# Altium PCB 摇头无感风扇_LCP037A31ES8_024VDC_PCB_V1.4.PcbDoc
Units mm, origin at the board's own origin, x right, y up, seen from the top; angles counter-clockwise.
Board outline 42.25 x 44.25 mm, 2 copper layers (Top Layer, Bottom Layer); 69 components, 48 nets, 179 pads, 190 vias.
Unrouted connection lines stored in the file: 31.
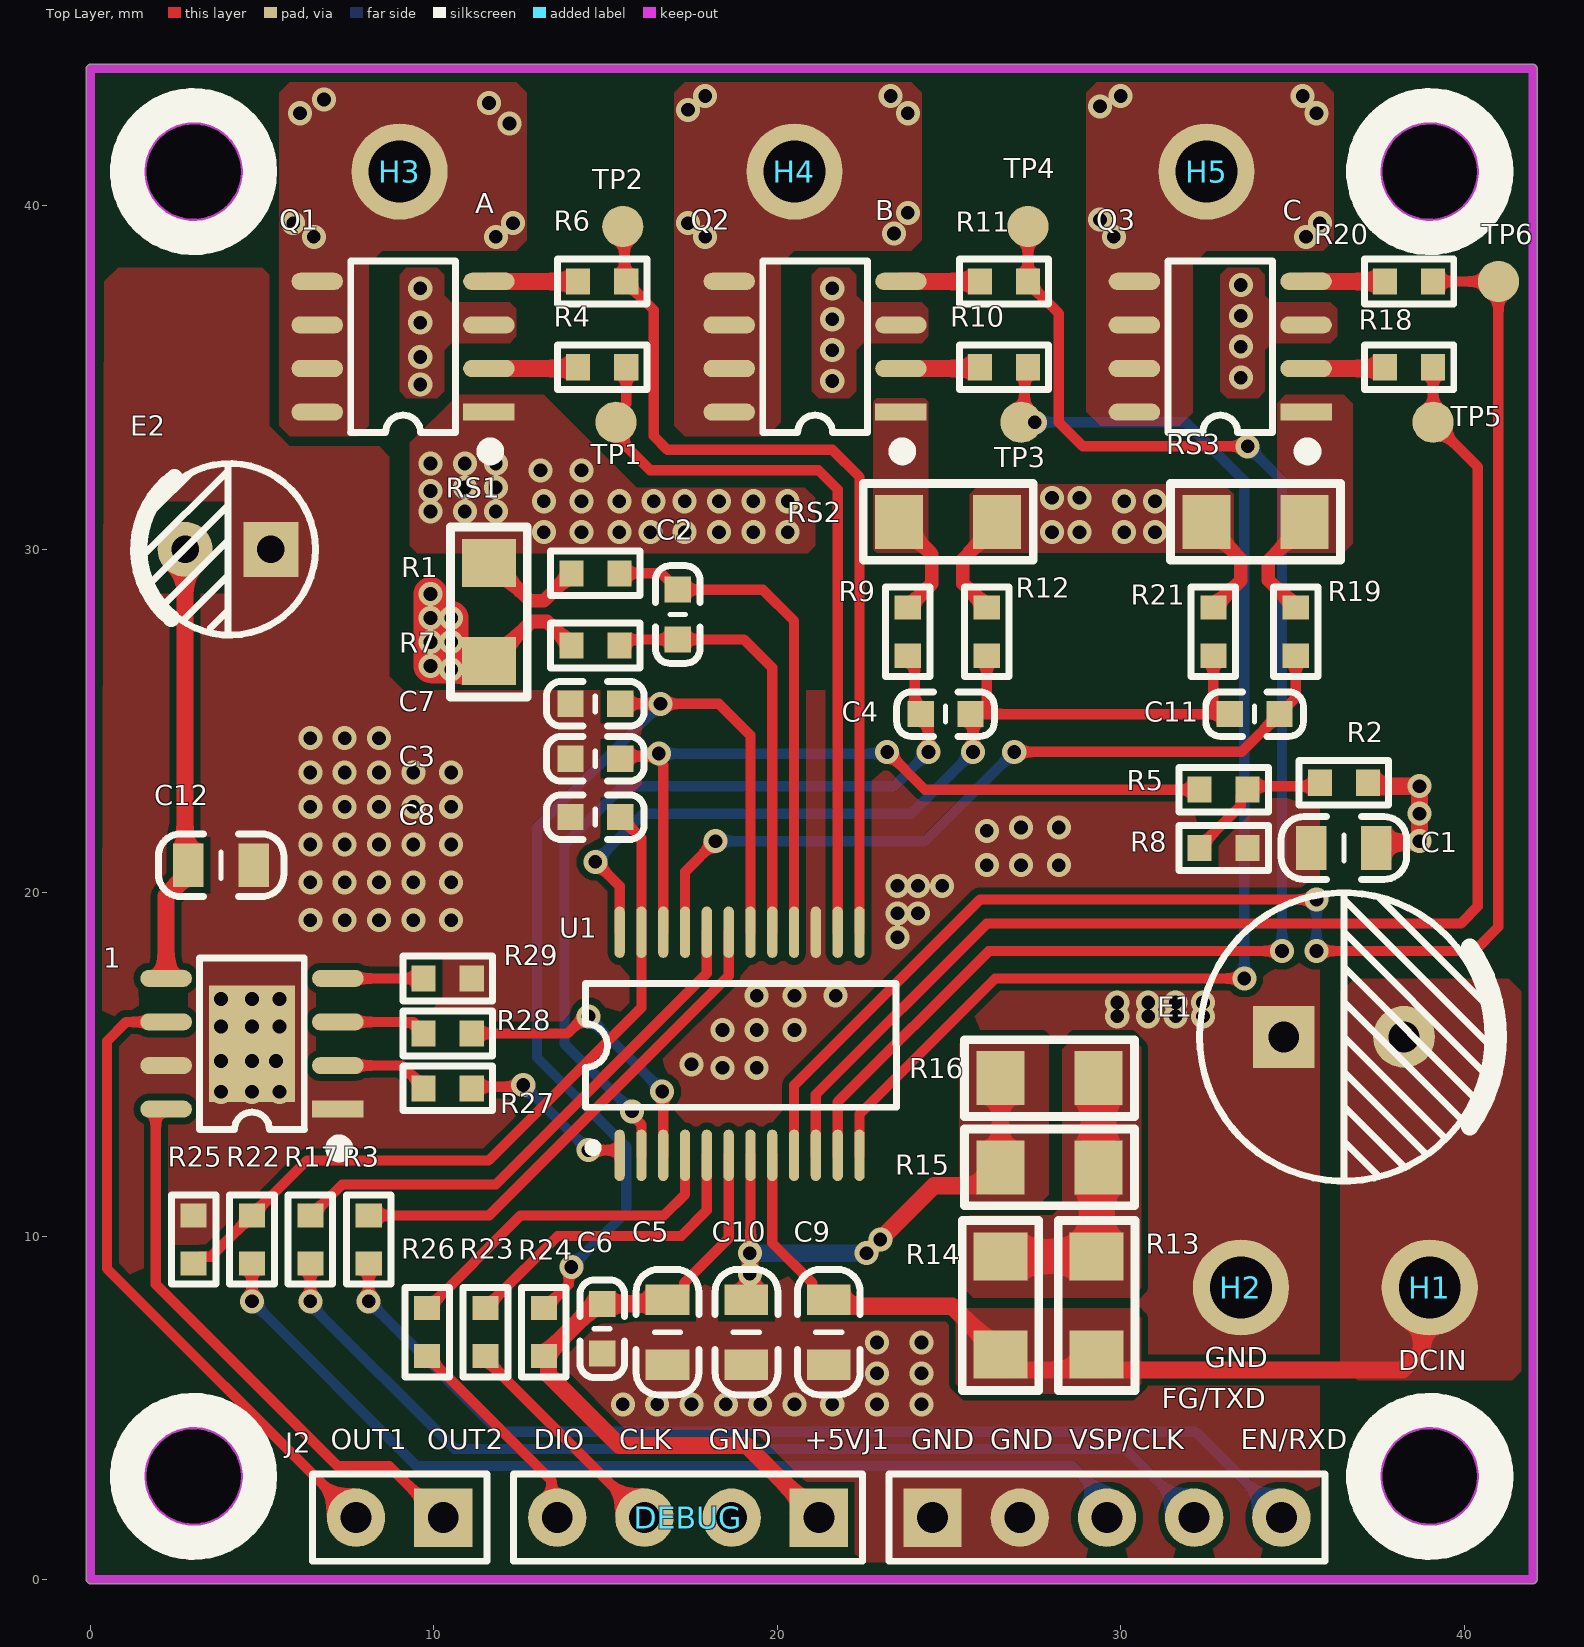
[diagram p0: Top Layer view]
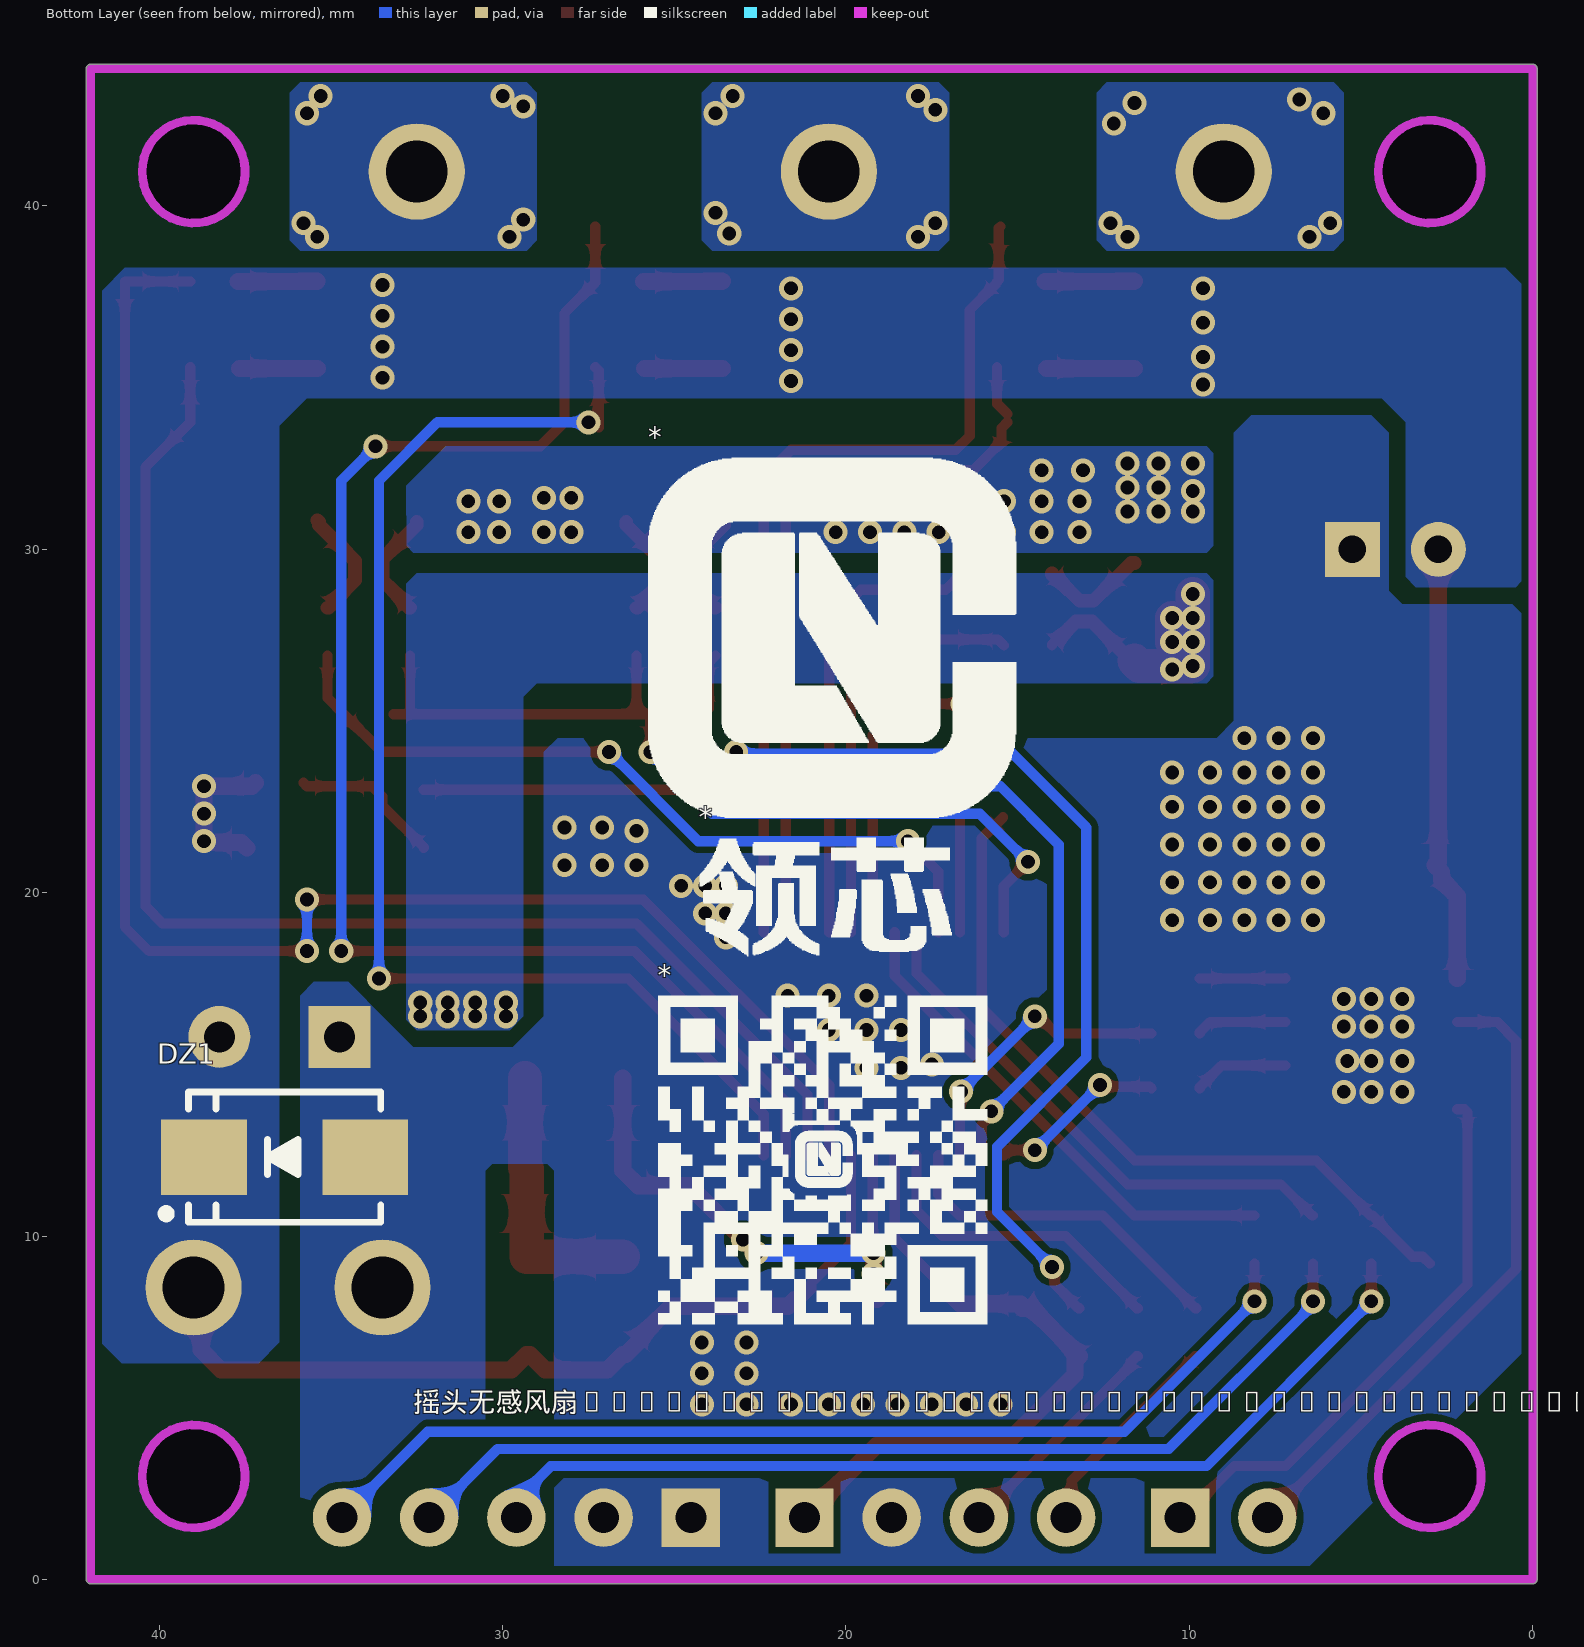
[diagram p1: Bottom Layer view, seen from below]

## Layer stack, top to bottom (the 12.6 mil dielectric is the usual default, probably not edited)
Top Solder: solder mask 0.0102, Solder Resist, Dk 3.5
Top Layer: signal copper 0.0356
Dielectric 1: dielectric 0.32, FR-4, Dk 4.8
Bottom Layer: signal copper 0.0356
Bottom Solder: solder mask 0.0102, Solder Resist, Dk 3.5

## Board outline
0,-0.127 cw(c0,0) -0.127,0 -0.127,44 cw(c0,44) 0,44.127 42,44.127 cw(c42,44) 42.127,44 42.127,0 cw(c42,0) 42,-0.127
cut-out: 37.5,3 ccw(c39,3) 39,1.5 ccw(c39,3) 40.5,3 ccw(c39,3) 39,4.5 ccw(c39,3)
cut-out: 3,1.5 cw(c3,3) 1.5,3 cw(c3,3) 3,4.5 cw(c3,3) 4.5,3 cw(c3,3)
cut-out: 39,39.5 cw(c39,41) 37.5,41 cw(c39,41) 39,42.5 cw(c39,41) 40.5,41 cw(c39,41)
cut-out: 3,39.5 cw(c3,41) 1.5,41 cw(c3,41) 3,42.5 cw(c3,41) 4.5,41 cw(c3,41)
cut-out: 1.5,3 ccw(c3,3) 3,1.5 ccw(c3,3) 4.5,3 ccw(c3,3) 3,4.5 ccw(c3,3)
cut-out: 37.5,41 ccw(c39,41) 39,39.5 ccw(c39,41) 40.5,41 ccw(c39,41) 39,42.5 ccw(c39,41)
cut-out: 1.5,41 ccw(c3,41) 3,39.5 ccw(c3,41) 4.5,41 ccw(c3,41) 3,42.5 ccw(c3,41)

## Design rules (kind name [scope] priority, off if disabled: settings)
Clearance [All] p1: gap=0.2 ignorepadtopadclearanceinfootprint=TRUE
ComponentClearance [All] p1: gap=0.15 collisioncheckmode=3 verticalgap=0.254 showdistances=FALSE
Height [All] p1: minheight=0 maxheight=200 prefheight=12.7
MinimumSolderMaskSliver [All] p1: minsoldermaskwidth=0.12
PlaneConnect [All] p1: planeconnectstyle=Direct reliefexpansion=0.508 reliefentries=4 reliefconductorwidth=0.254 reliefairgap=0.254
PolygonConnect [All] p1: connectstyle=Direct reliefconductorwidth=0.254 reliefentries=4 polygonreliefangle="90 Angle" airgapwidth=0.254
RoutingVias [All] p1: holewidth=0.4 width=0.7 viastyle="Through Hole" minholewidth=0.305 minwidth=0.508 maxholewidth=0.711 maxwidth=1.27
SilkToSilkClearance [All] p1: silktosilkclearance=0.1
SilkToSolderMaskClearance [IsPad] p1: minsilkscreentomaskgap=0.05 clearancetoexposedcopper=TRUE
SolderMaskExpansion [IsVia] p1: expansion=0.102 istentingtop=TRUE useseparateexpansions=TRUE expansionbottom=0.102 istentingbottom=TRUE
Width [All] p1: maxlimit=1.27 minlimit=0.2 preferedwidth=0.3
24 further rules are at their usual default settings.

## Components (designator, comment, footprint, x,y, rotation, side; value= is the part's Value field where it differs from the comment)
1 "KP8110X" SOP-8_150_50-1 4.7,15.6 r180 top
* "LOGO-TU" LOGO-TU 20.4,26.5 r180 bottom
* "LOGO-ZI" LOGO-ZI 20.6,20.1 r180 bottom
* "LOGO-MA" LOGO-MA 20.6,12.2 r180 bottom
C1 "104/50V" C0805 36.5,21.3 r0 top
C2 "101/50V" C0603 17.1,28.1 r90 top
C3 "103/50V" C0603 14.7,23.9 r0 top
C4 "101/50V" C0603 24.9,25.2 r180 top
C5 "106/50V" C0805 16.8,7.2 r90 top
C6 "104/50V" C0603 14.9,7.3 r90 top
C7 "104/50V" C0603 14.7,25.5 r0 top
C8 "101/50V" C0603 14.7,22.2 r0 top
C9 "104/50V" C0805 21.5,7.2 r90 top
C10 "105/50V" C0805 19.1,7.2 r90 top
C11 "101/50V" C0603 33.9,25.2 r0 top
C12 "104/50V" C0805 3.8,20.8 r0 top
DEBUG "CON4-a" PZ2.54-D-4P 17.4,1.8 r180 top
DZ1 "28V" SMB 36.35,12.3 r0 bottom
E1 "220uF/35V" CE-3.5-8 36.5,15.8 r0 top
E2 "100uF/35V" CE-2.5-5 4,30 r180 top
H1 "DCIN" HOLD-16AWG 39,8.5 r0 top
H2 "GND" HOLD-16AWG 33.5,8.5 r0 top
H3 "A" HOLD-16AWG 9,41 r0 top
H4 "B" HOLD-16AWG 20.5,41 r0 top
H5 "C" HOLD-16AWG 32.5,41 r0 top
J1 "CON5" PZ2.54-D-5P 29.6,1.8 r0 top
J2 "CON2" PZ2.54-D-2P 9,1.8 r180 top
Q1 "4606" SOP-8_150_50 9.1,35.9 r180 top
Q2 "4606" SOP-8_150_50 21.1,35.9 r180 top
Q3 "4606" SOP-8_150_50 32.9,35.9 r180 top
R1 "68R" R0603 14.7,29.3 r0 top
R2 "100K" R0603 36.5,23.2 r0 top
R3 "1K" R0603 8.1,9.9 r90 top
R4 "51R" R0603 14.9,35.3 r180 top
R5 "1K" R0603 33,23 r180 top
R6 "51R" R0603 14.9,37.8 r180 top
R7 "68R" R0603 14.7,27.2 r0 top
R8 "10K" R0603 33,21.3 r180 top
R9 "68R" R0603 23.8,27.6 r270 top
R10 "51R" R0603 26.6,35.3 r180 top
R11 "51R" R0603 26.6,37.8 r180 top
R12 "68R" R0603 26.1,27.6 r270 top
R13 "1K/1206" R1206 29.3,8 r270 top
R14 "1K/1206" R1206 26.5,8 r270 top
R15 "680R/1206" R1206 27.9,12 r0 top
R16 "680R/1206" R1206 27.9,14.6 r0 top
R17 "10K" R0603 6.4,9.9 r90 top
R18 "51R" R0603 38.4,35.3 r180 top
R19 "68R" R0603 35.1,27.6 r270 top
R20 "51R" R0603 38.4,37.8 r180 top
R21 "68R" R0603 32.7,27.6 r270 top
R22 "1K" R0603 4.7,9.9 r90 top
R23 "100R" R0603 11.5,7.2 r90 top
R24 "10K" R0603 13.2,7.2 r270 top
R25 "10K" R0603 3,9.9 r270 top
R26 "100R" R0603 9.8,7.2 r90 top
R27 "1K" R0603 10.4,14.3 r180 top
R28 "1K" R0603 10.4,15.9 r180 top
R29 "1K" R0603 10.4,17.5 r180 top
RS1 "0.05R/1206" R1206 11.6,28.15 r90 top
RS2 "0.05R/1206" R1206 25,30.8 r180 top
RS3 "0.05R/1206" R1206 33.9,30.8 r0 top
TP1 "TEST" "TP 1.2" 15.3,33.7 r90 top
TP2 "TEST" "TP 1.2" 15.5,39.4 r90 top
TP3 "TEST" "TP 1.2" 27.1,33.7 r90 top
TP4 "TEST" "TP 1.2" 27.3,39.4 r90 top
TP5 "TEST" "TP 1.2" 39.1,33.7 r90 top
TP6 "TEST" "TP 1.2" 41,37.8 r90 top
U1 "LCP037A31ES8" LNCP-SSOP24-0.635 18.9,15.6 r90 top locked

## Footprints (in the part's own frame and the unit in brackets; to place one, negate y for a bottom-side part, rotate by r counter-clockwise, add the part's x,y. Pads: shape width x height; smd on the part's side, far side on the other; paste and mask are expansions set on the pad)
C0603 [mil] "0.5/2.1"
  rect 30x30 smd: 1(-28.54,0) 2(28.54,0)
  silkscreen extent -56,-26 56,26, body extent -31,-16 32,16, height 33
C0805 [mil] "贴片MLCC电容"
  rect 35x50 smd: 1(-37.4,0) 2(37.4,0)
  silkscreen extent -72,-36 72,36, body extent -39,-24 39,24, height 22
CE-2.5-5 [mm] "直插电解电容-脚距2.5mm直径5mm高度11mm"
  rect 1.6x1.6 hole 0.8: 1(-1.25,0)
  round 1.6 hole 0.8: 2(1.25,0)
  silkscreen extent -2.55,-2.5 2.6,2.5, body extent -2.5,-2.5 2.51,2.5, height 11.14
CE-3.5-8 [mm] "脚距3.5mm直径8mm高度11.5mm"
  rect 1.8x1.8 hole 0.9: 1(-1.75,0)
  round 1.8 hole 0.9: 2(1.75,0)
  silkscreen extent -4.2,-4.2 4.5,4.2, body extent -4,-4 4.01,4, height 11.64
HOLD-16AWG [mm] "1.8mm"
  round 2.8 hole 1.8: 1(0,0)
LNCP-SSOP24-0.635 [mm] "电机专用MCU-LCP037AH31E(X)S8/LCP018AH31E(X)S8"
  oval 1.5x0.3 smd: 1(-3.25,3.492) 2(-3.25,2.857) 3(-3.25,2.222) 4(-3.25,1.587) 5(-3.25,0.952) 6(-3.25,0.317) 7(-3.25,-0.318) 8(-3.25,-0.953) 9(-3.25,-1.588) 10(-3.25,-2.223) 11(-3.25,-2.858) 12(-3.25,-3.492) 13(3.25,-3.492) 14(3.25,-2.857) 15(3.25,-2.222) 16(3.25,-1.587) 17(3.25,-0.952) 18(3.25,-0.317) 19(3.25,0.318) 20(3.25,0.953) 21(3.25,1.588) 22(3.25,2.223) 23(3.25,2.858) 24(3.25,3.492)
  silkscreen extent -3.15,-4.57 1.75,4.48
LOGO-MA [mm]
  silkscreen extent -4.87,-4.77 4.71,4.78
LOGO-TU [mm]
  silkscreen extent -5.36,-4.32 5.36,6.15
LOGO-ZI [mm]
  silkscreen extent -3.67,-1.95 3.67,1.48
PZ2.54-D-2P [mm]
  rect 1.7x1.7 hole 0.9: 1(-1.27,0)
  round 1.7 hole 0.9: 2(1.27,0)
  silkscreen extent -2.54,-1.27 2.54,1.27, body extent -2.54,-1.27 2.54,1.27, height 2.54
PZ2.54-D-4P [mm]
  rect 1.7x1.7 hole 0.9: 1(-3.81,0)
  round 1.7 hole 0.9: 2(-1.27,0) 3(1.27,0) 4(3.81,0)
  silkscreen extent -5.08,-1.27 5.08,1.27, body extent -5.08,-1.27 5.08,1.27, height 2.54
PZ2.54-D-5P [mm]
  rect 1.7x1.7 hole 0.9: 1(-5.08,0)
  round 1.7 hole 0.9: 2(-2.54,0) 3(0,0) 4(2.54,0) 5(5.08,0)
  silkscreen extent -6.35,-1.27 6.35,1.27, body extent -6.35,-1.27 6.35,1.27, height 2.54
R0603 [mm] "0.5/2.1"
  rect 0.7x0.762 smd: 1(-0.7,0) 2(0.7,0)
  silkscreen extent -1.3,-0.65 1.3,0.65, body extent -0.8,-0.4 0.8,0.4, height 0.4
R1206 [mil] "1/4W贴片电阻"
  rect 55x62 smd: 1(-55.12,0) 2(57.09,0)
  silkscreen extent -96,-44 98,44, body extent -63,-31 63,32, height 22
SMB [mm] "4.7*3.9*2.2mm"
  rect 2.5x2.2 smd: 1(-2.35,0) 2(2.35,0)
  silkscreen extent -2.8,-1.9 3.58,1.9, body extent -2.65,-1.8 2.65,1.8, height 2.35
SOP-8_150_50 [mm] "无焊盘"
  rect 1.5x0.5 smd: 1(-2.5,1.905)
  oval 1.5x0.5 smd: 2(-2.5,0.635) 3(-2.5,-0.635) 4(-2.5,-1.905) 5(2.5,-1.905) 6(2.5,-0.635) 7(2.5,0.635) 8(2.5,1.905)
  silkscreen extent -2.69,-2.5 1.52,3.2, body extent -3,-2.5 3,2.5
SOP-8_150_50-1 [mm] "5*6*1.8mm（长宽高）"
  rect 1.5x0.5 smd: 1(-2.5,1.905)
  oval 1.5x0.5 smd: 2(-2.5,0.635) 3(-2.5,-0.635) 4(-2.5,-1.905) 5(2.5,-1.905) 6(2.5,-0.635) 7(2.5,0.635) 8(2.5,1.905)
  rect 2.5x3.4 smd paste-2: 9(0,0)
  rect 0.9x0.7 on Top Paste: 10(-0.625,1.1) 10(-0.625,0) 10(-0.625,-1.1) 11(0.65,1.1) 11(0.65,0) 11(0.65,-1.1)
  silkscreen extent -2.69,-2.5 1.52,3.2, body extent -3,-2.5 3,2.5
"TP 1.2" [mm] "测试点1.2mm"
  round 1.2 smd paste-1.2: 1(0,0)

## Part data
C1 C5 C9 C10 C12: library part CAP_8, "0805"
C2 C3 C4 C6 C7 C8 C11: library part CAP_4/6, "0402/0603"
DEBUG: "烧录口"
DZ1: library part DIO_ZENER, "稳压管"
E1 E2: library part CAP_CE, "直插电解电容"
H1 H2 H3 H4 H5: library part HOLD
J1 J2: "排针排母"
Q1 Q2 Q3: library part TRA_MOS_8D, "8脚合封组合"
R1 R2 R3 R4 R5 R6 R7 R8 R9 R10 R11 R12 R17 R18 R19 R20 R21 R22 R23 R24 R25 R26 R27 R28 R29: library part RES_4/6, "0402/0603"
R13 R14 R15 R16 RS1 RS2 RS3: library part RES_12/18, "1206/1802"
TP1 TP2 TP3 TP4 TP5 TP6: library part TEST1, "测试点"
U1: library part MCU_电机专用-5, "LCP037A"

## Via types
v1: diameter 0.7, hole 0.4, Top Layer to Bottom Layer, tented both sides, 190 vias

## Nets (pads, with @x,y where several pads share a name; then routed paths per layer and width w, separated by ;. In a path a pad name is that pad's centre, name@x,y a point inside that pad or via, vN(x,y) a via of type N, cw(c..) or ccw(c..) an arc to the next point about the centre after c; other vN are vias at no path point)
+5V: C5.2 C6.2 DEBUG.1 R24.2 U1.6 | length 19.5
  Top Layer w0.3: C5.2@16.869,8.219 17.059,8.219 17.285,8.444 17.285,8.635 18.583,9.932 U1.6
  Top Layer w0.5: C6.2@14.9,7.925 14.869,7.894 14.594,7.894 13.331,6.631 13.331,6.6 R24.2@13.231,6.5 ; C6.2 16.675,8.025 C5.2@16.869,8.219 ; DEBUG.1 19.11,3.9 15.4,3.9 13.331,5.969 13.331,6.4 R24.2@13.231,6.5 ; R24.2@13.231,6.5 R24.2 R24.2@13.231,6.5
+24V: 1.5 C1.2 C9.2 C12.1 DZ1.2 E1.2 E2.2 H1.1 Q1.3 Q2.3 Q3.3 R2.2 R13.2 R14.2 U1.8 | length 42.9
  Top Layer w0.3: U1.8 19.853,9.798 21.015,8.635 21.015,8.444 21.31,8.15 C9.2
  Top Layer w0.5: 1.5 2.2,19.9 2.655,20.355 2.655,20.605 C12.1 2.75,20.9 E2.2 ; C9.2 21.695,7.955 25.095,7.955 25.963,7.087 25.963,6.999 R14.2@26.411,6.55 ; R14.2 26.949,6.101 27.329,6.101 27.33,6.1 28.761,6.1 29.211,6.55 R13.2 29.749,6.101 30.129,6.101 30.13,6.1 38.2,6.1 38.78,6.68 38.78,8.28 H1.1 ; R2.2 37.3,23.1 v1(38.7,23.1) v1(38.7,22.3) v1(38.7,21.5) 38.662,21.462 37.612,21.462 C1.2
  other v1: 9.6,34.8 21.6,34.9 33.5,35 9.6,35.6 21.6,35.8 33.5,35.9 9.6,36.6 21.6,36.7 33.5,36.8 9.6,37.6 21.6,37.6 33.5,37.7
AH: R20.1 TP6.1 U1.9 | length 47.3
  Top Layer w0.3: U1.9 20.488,14.387 25.9,19.8 v1(35.7,19.8) ; v1(35.7,18.3) 40.3,18.3 41,19 TP6.1 R20.1
  Bottom Layer w0.3: v1(35.7,18.3) v1(35.7,19.8)
AL: R18.1 TP5.1 U1.10 | length 39.6
  Top Layer w0.3: U1.10 21.123,14.122 26.1,19.1 39.9,19.1 40.4,19.6 40.4,32.4 TP5.1 R18.1
BH: R11.1 TP4.1 U1.11 | length 43.3
  Top Layer w0.3: U1.11 21.758,13.905 26.153,18.3 v1(34.7,18.3) ; TP4.1 R11.1 27.3,37.769 28.2,36.869 28.2,33.7 28.9,33 v1(33.7,33)
  Bottom Layer w0.3: v1(33.7,33) 34.7,32 v1(34.7,18.3)
BL: R10.1 TP3.1 U1.12 | length 37.5
  Top Layer w0.3: U1.12 22.393,13.55 26.342,17.5 v1(33.6,17.5) ; R10.1 27.2,35.2 27.2,33.55 27.35,33.7 v1(27.5,33.7)
  Bottom Layer w0.3: v1(27.5,33.7) 31.9,33.7 33.6,32 v1(33.6,17.5)
CH: R6.1 TP2.1 U1.13 | length 26.2
  Top Layer w0.3: TP2.1 15.55,39.35 15.55,37.85 R6.1 15.6,37.769 16.4,36.969 16.4,33.3 16.8,32.9 21.6,32.9 22.393,32.107 U1.13
CL: R4.1 TP1.1 U1.14 | length 21.9
  Top Layer w0.3: TP1.1 15.472,33.528 15.472,33.128 16.3,32.3 21.2,32.3 21.758,31.743 U1.14 ; TP1.1@15.3,33.944 15.6,34.244 R4.1
EN/RXD: R3.2 U1.19 | length 14.6
  Top Layer w0.3: R3.2 11.607,10.6 18.583,17.575 U1.19
FG/TXD: R17.2 U1.20 | length 15.7
  Top Layer w0.3: R17.2 6.431,10.6 7.331,11.5 11.8,11.5 17.948,17.648 U1.20
GND: 1.1 1.7 1.9 C1.1 C3.1 C5.1 C6.1 C7.1 C8.1 C9.1 C10.1 C12.2 DEBUG.2 DZ1.1 E1.1 E2.1 H2.1 J1.1 J1.2 R7.1 R8.1 R25.1 R29.1 RS1.1 U1.15 | length 7.7
  Top Layer w0.3: RS1.1 RS1.1@11.689,26.75 ; R7.1@13.769,27.431 13.8,27.431 14,27.231 R7.1
  Top Layer w0.4: RS1.1@11.689,26.75 12.839,27.9 13.3,27.9 R7.1@13.769,27.431
  Top Layer w1: v1(9.9,28.7) v1(9.9,26.6) 11.45,26.6 RS1.1 ; v1(10.5,27.3) v1(10.5,28)
  other v1: 15.5,5.1 16.5,5.1 17.5,5.1 18.5,5.1 19.5,5.1 20.5,5.1 21.6,5.1 22.9,5.1 24.2,5.1 22.9,6 24.2,6 22.9,6.9 24.2,6.9 3.8,14.2 4.7,14.2 5.5,14.2 18.4,14.9 19.4,14.9 17.5,15 3.8,15.1 4.7,15.1 5.4,15.1 18.4,16 19.4,16 20.5,16 3.8,16.1 4.7,16.1 5.5,16.1 29.9,16.4 30.8,16.4 31.6,16.4 32.4,16.4 29.9,16.8 30.8,16.8 31.6,16.8 32.4,16.8 3.8,16.9 4.7,16.9 5.5,16.9 19.4,17 20.5,17 21.7,17 23.5,18.7 6.4,19.2 7.4,19.2 8.4,19.2 9.4,19.2 10.5,19.2 23.5,19.4 24.1,19.4 23.5,20.2 24.1,20.2 24.8,20.2 6.4,20.3 7.4,20.3 8.4,20.3 9.4,20.3 10.5,20.3 26.1,20.8 27.1,20.8 28.2,20.8 6.4,21.4 7.4,21.4 8.4,21.4 9.4,21.4 10.5,21.4 26.1,21.8 27.1,21.9 28.2,21.9 6.4,22.5 7.4,22.5 8.4,22.5 9.4,22.5 10.5,22.5 6.4,23.5 7.4,23.5 8.4,23.5 9.4,23.5 10.5,23.5 6.4,24.5 7.4,24.5 8.4,24.5 10.5,26.5 9.9,27.3 9.9,28
MA: R27.1 U1.1 | length 5.3
  Top Layer w0.3: R27.1 11.15,14.35 12.55,14.35 v1(12.6,14.4) ; v1(14.5,12.5) 15.408,12.5 U1.1
  Bottom Layer w0.3: v1(12.6,14.4) v1(14.5,12.5)
MB: R28.1 U1.3 | length 8.6
  Top Layer w0.3: R28.1 13.892,15.9 14.392,16.4 v1(14.5,16.4) ; v1(16.646,14.208) 16.678,14.177 U1.3
  Bottom Layer w0.3: v1(14.5,16.4) 14.5,16.377 16.646,14.231 v1(16.646,14.208)
Net1_2: 1.2 R27.2 | length 2.8
  Top Layer w0.3: 1.2 9.066,14.965 9.7,14.331 R27.2
Net1_3: 1.3 R28.2 | length 2.7
  Top Layer w0.3: 1.3 9.396,16.235 9.7,15.931 R28.2
Net1_4: 1.4 R29.2 | length 2.5
  Top Layer w0.3: 1.4 7.203,17.502 9.698,17.502 R29.2
Net1_6: 1.6 J2.2 | length 18.7
  Top Layer w0.3: 1.6 1.035,16.235 0.477,15.677 0.477,9.053 7.273,2.257 7.687,2.257 J2.2@7.73,2.3
Net1_8: 1.8 J2.1 | length 16.5
  Top Layer w0.3: 1.8 1.992,13.695 1.9,13.603 1.9,8.6 7.2,3.3 8.7,3.3 9.5,2.5 9.57,2.5 J2.1
NetDEBUG_3: DEBUG.3 R23.1 | length 6.6
  Top Layer w0.3: R23.1 11.531,6.5 11.731,6.3 11.731,6.199 DEBUG.3
NetDEBUG_4: DEBUG.4 R26.1 | length 6.3
  Top Layer w0.3: R26.1 9.831,6.5 10.031,6.3 10.031,6.269 13.426,2.874 13.426,1.964 DEBUG.4
NetH3_1: H3.1 Q1.5 Q1.6 Q1.7 Q1.8
  other v1: 6.5,39.1 11.8,39.1 5.9,39.5 12.3,39.5 12.2,42.4 6.1,42.7 11.6,43 6.8,43.1
NetH4_1: H4.1 Q2.5 Q2.6 Q2.7 Q2.8
  other v1: 17.9,39.1 23.4,39.2 17.4,39.5 23.8,39.8 23.8,42.7 17.4,42.8 17.9,43.2 23.3,43.2
NetH5_1: H5.1 Q3.5 Q3.6 Q3.7 Q3.8
  other v1: 29.8,39.1 35.4,39.1 35.8,39.5 29.4,39.6 35.7,42.7 29.4,42.9 30,43.2 35.3,43.2
NetJ1_3: J1.3 R22.1 | length 28.4
  Top Layer w0.3: v1(4.7,8.1) R22.1
  Bottom Layer w0.3: v1(4.7,8.1) 9.5,3.3 28.6,3.3 J1.3@29.6,2.3
NetJ1_4: J1.4 R17.1 | length 29.5
  Top Layer w0.3: v1(6.4,8.1) R17.1
  Bottom Layer w0.3: v1(6.4,8.1) 6.4,8 10.6,3.8 30.14,3.8 J1.4
NetJ1_5: J1.5 R3.1 | length 30.3
  Top Layer w0.3: v1(8.1,8.1) R3.1
  Bottom Layer w0.3: v1(8.1,8.1) 11.9,4.3 32.18,4.3 J1.5
NetQ1_1: Q1.1 R1.1 R12.1 R21.1 RS1.2 RS2.1 RS3.1 | length 9.7
  Top Layer w0.4: RS1.2 11.689,29.6 12.789,28.5 13.2,28.5 13.819,29.119 13.85,29.119 14,29.269 R1.1 ; R12.1 26.069,28.3 25.869,28.5 25.869,28.531 25.4,29 25.4,29.711 26.4,30.711 RS2.1 ; RS3.1 32.5,30.711 33.5,29.711 33.5,29.1 32.931,28.531 32.931,28.5 32.731,28.3 R21.1
  other v1: 13.2,30.5 14.3,30.5 15.4,30.5 16.3,30.5 17.3,30.5 18.3,30.5 19.3,30.5 20.3,30.5 28,30.5 28.8,30.5 30.1,30.5 31,30.5 9.9,31.1 10.9,31.1 11.8,31.1 13.2,31.4 14.3,31.4 15.4,31.4 16.4,31.4 17.3,31.4 18.3,31.4 19.3,31.4 20.3,31.4 30.1,31.4 31,31.4 28,31.5 28.8,31.5 9.9,31.7 10.9,31.8 11.8,31.8 13.1,32.3 14.3,32.3 9.9,32.5 10.9,32.5 11.8,32.5
NetQ1_2: Q1.2 R4.2 | length 2.6
  Top Layer w0.3: R4.2@14.182,35.283 R4.2
  Top Layer w0.5: Q1.2 R4.2@14.165,35.265
NetQ1_4: Q1.4 R6.2 | length 2.6
  Top Layer w0.3: Q1.4 Q1.4@11.602,37.803
  Top Layer w0.5: Q1.4@11.605,37.805 12.1,37.805 12.105,37.8 R6.2
NetQ2_1: Q2.1 R9.1 RS2.2 | length 3.3
  Top Layer w0.4: RS2.2 23.55,30.711 24.049,30.213 24.137,30.213 24.5,29.85 24.5,29 23.981,28.481 23.981,28.45 23.831,28.3 R9.1
NetQ2_2: Q2.2 R10.2 | length 2.3
  Top Layer w0.3: R10.2@25.882,35.283 R10.2
  Top Layer w0.5: Q2.2 R10.2@25.865,35.265
NetQ2_4: Q2.4 R11.2 | length 2.3
  Top Layer w0.3: Q2.4 Q2.4@23.602,37.803
  Top Layer w0.5: Q2.4@23.605,37.805 24.1,37.805 24.105,37.8 R11.2
NetQ3_1: Q3.1 R19.1 RS3.2 | length 3.4
  Top Layer w0.4: R19.1 35.069,28.3 34.869,28.5 34.869,28.531 34.3,29.1 34.3,29.661 35.35,30.711 RS3.2 RS3.2@35.4,30.85
NetQ3_2: Q3.2 R18.2 | length 2.3
  Top Layer w0.3: R18.2@37.682,35.283 R18.2
  Top Layer w0.5: Q3.2 R18.2@37.665,35.265
NetQ3_4: Q3.4 R20.2 | length 2.3
  Top Layer w0.3: Q3.4 Q3.4@35.402,37.803
  Top Layer w0.5: Q3.4@35.405,37.805 35.9,37.805 35.905,37.8 R20.2
NetR2_1: R2.1 R5.1 R8.2 | length 4.5
  Top Layer w0.3: R8.2 32.3,21.331 33.5,22.531 33.5,22.8 R5.1 33.8,23.1 35.7,23.1 R2.1
NetR13_1: R13.1 R14.1 R15.2 R16.2 | length 7.9
  Top Layer w1: R14.1 R13.1 R15.2@29.3,11.95 ; R15.2 R16.2
NRST: C7.2 R24.1 U1.18 | length 31.1
  Top Layer w0.3: R24.1 13.231,7.9 13.923,8.593 13.923,9.023 v1(14,9.1) ; C7.2 v1(16.6,25.5) 18.3,25.5 19.218,24.583 U1.18
  Bottom Layer w0.3: v1(14,9.1) 15.6,10.7 15.6,12.6 13,15.2 13,21.9 v1(16.6,25.5)
OPA0_IN/OPA2_IN: C4.1 C11.1 R12.2 R21.2 U1.24 | length 26.8
  Top Layer w0.3: v1(14.7,20.9) 15.408,20.192 U1.24 ; v1(25.7,24.1) 25.7,25.125 C4.1 26.1,25.2 ; R12.2 26.1,25.2 ; R21.2 32.7,25.3 C11.1@32.8,25.2 ; C11.1 C11.1@32.8,25.2 ; 26.1,25.2 C11.1@32.8,25.2
  Bottom Layer w0.3: v1@14.716,20.916 16.1,22.3 23.9,22.3 v1(25.7,24.1)
OPA0_IP: C11.2 R19.2 U1.21 | length 22.9
  Top Layer w0.3: U1.21 17.313,20.613 v1(18.2,21.5) ; v1(26.9,24.1) 33.525,24.1 C11.2 35.1,25.675 R19.2
  Bottom Layer w0.3: v1(18.2,21.5) 24.3,21.5 v1(26.9,24.1)
OPA1_IN: C2.1 R7.2 U1.17 | length 12.6
  Top Layer w0.3: R7.2 15.575,27.375 C2.1 19.025,27.375 19.853,26.548 U1.17
OPA1_IP: C2.2 R1.2 U1.16 | length 14.7
  Top Layer w0.3: R1.2 16.625,29.3 C2.2 19.575,28.825 20.488,27.913 U1.16
OPA2_IP: C4.2 R9.2 U1.2 | length 24.8
  Top Layer w0.3: v1(15.767,13.633) 15.767,13.524 16.043,13.249 U1.2 ; R9.2 24,26.7 24,25.375 C4.2@24.188,25.188 ; C4.2 24.4,24.975 v1(24.4,24.1)
  Bottom Layer w0.3: v1(15.767,13.633) 13.8,15.6 13.8,21.4 15.5,23.1 23.4,23.1 v1(24.4,24.1)
SWCLK: R23.2 U1.5 | length 9.2
  Top Layer w0.3: R23.2 11.531,7.9 11.731,8.1 11.731,8.131 13.6,10 17.2,10 17.948,10.747 U1.5
SWDIO: R26.2 U1.4 | length 10
  Top Layer w0.3: R26.2 9.831,7.9 12.531,10.6 16.7,10.6 17.313,11.213 U1.4
Vbus: C3.2 R5.2 U1.22 | length 22.7
  Top Layer w0.3: C3.2 15.5,23.975 16.475,23.975 v1(16.55,24.05) 16.627,23.973 16.627,23.765 16.678,23.714 U1.22 ; v1(23.2,24.1) 24.3,23 R5.2
  Bottom Layer w0.3: v1(16.55,24.05) 23.15,24.05 v1(23.2,24.1)
VCCP: C10.2 R15.1 R16.1 U1.7 | length 15.2
  Top Layer w0.3: v1@19.218,9.5 U1.7
  Top Layer w0.5: C10.2 19.2,8.25 19.2,9.482 v1@19.218,9.5 ; v1(22.6,9.5) v1(23,9.9) 24.563,11.463 26.051,11.463 26.5,11.911 R16.1
  Bottom Layer w0.5: v1(19.2,9.5) v1(22.6,9.5)
  other v1: 19.2,8.9
VSP/CLK: C8.2 R22.2 R25.2 U1.23 | length 22
  Top Layer w0.3: R25.2 3.2,9.4 3.5,9.4 4.469,10.369 4.469,10.4 4.669,10.6 4.731,10.6 4.931,10.8 4.931,10.831 6.3,12.2 11.59,12.2 16.043,16.653 U1.23 16.043,21.582 C8.2
pads on no net: 1.10 1.11

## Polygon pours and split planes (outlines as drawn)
GND on Top Layer "GND_L01_P027" (solid, remove dead copper, pour order 27): 0.4,37.8 0.8,38.2 5,38.2 5.2,38 5.2,33.6 5.8,33 8.4,33 8.7,32.7 8.7,26.3 9.1,25.9 35.3,25.9 35.8,25.4 35.8,1.1 35.2,0.5 6.5,0.5 0.3,6.7 0.3,9.5
NetR13_1 on Top Layer "NETR13_1_L01_P019" (solid, remove dead copper, pour order 19): 25.7,8.2 30.3,8.2 30.6,8.5 30.6,15.5 30.3,15.8 28.664,15.8 28.3,15.436 28.3,10.9 28,10.6 25.6,10.6 25.3,10.3 25.3,8.6
+24V on Top Layer "+24V_L01_P020" (solid, remove dead copper, pour order 20): 25.2,5.7 25.5,5.4 30.3,5.4 30.6,5.7 30.6,7.6 30.3,7.9 25.5,7.9 25.2,7.6
NetQ1_1 on Top Layer "NETQ1_1_L01_P018" (solid, remove dead copper, pour order 18): 9.514,29.886 9.3,30.1 9.3,33.1 10.7,34.5 13.2,34.5 15.9,31.8 20.8,31.8 21.1,31.5 21.1,30.1 20.886,29.886
+24V on Top Layer "+24V_L01_P017" (solid, remove dead copper, pour order 17): 36.4,17.1 36.8,17.5 41.3,17.5 41.7,17.1 41.7,6.1 41.4,5.8 36.9,5.8 36.4,6.3
VCCP on Top Layer "VCCP_L01_P016" (solid, remove dead copper, pour order 16): 25.8,11 27.7,11 27.9,11.2 27.9,15.6 27.7,15.8 25.5,15.8 25.3,15.6 25.3,11.3 25.6,11
NetH5_1 on Top Layer "NETH5_1_L01_P015" (solid, remove dead copper, pour order 15): 31.727,33.6 32.1,33.973 32.1,38.3 32.5,38.7 35.9,38.7 36.2,39 36.2,43.3 35.9,43.6 29.3,43.6 29,43.3 29,34 29.4,33.6
NetH4_1 on Top Layer "NETH4_1_L01_P014" (solid, remove dead copper, pour order 14): 19.7,33.3 20.1,33.7 20.1,38.3 20.5,38.7 23.9,38.7 24.2,39 24.2,43.3 23.9,43.6 17.3,43.6 17,43.3 17,33.6 17.3,33.3
NetH3_1 on Top Layer "NETH3_1_L01_P013" (solid, remove dead copper, pour order 13): 7.8,33.3 8.1,33.6 8.1,38.3 8.5,38.7 12.4,38.7 12.7,39 12.7,43.3 12.4,43.6 5.8,43.6 5.5,43.3 5.5,33.6 5.8,33.3
+24V on Top Layer "+24V_L01_P012" (solid, remove dead copper, pour order 12): 12.2,37.2 12.4,37 12.4,36.2 12.2,36 10.5,36 10.3,35.8 10.3,34.6 10.1,34.4 9.2,34.4 9,34.6 9,38 9.2,38.2 10.1,38.2 10.3,38 10.3,37.4 10.5,37.2
+24V on Top Layer "+24V_L01_P011" (solid, remove dead copper, pour order 11): 24.2,37.2 24.4,37 24.4,36.2 24.2,36 22.5,36 22.3,35.8 22.3,34.6 22.1,34.4 21.2,34.4 21,34.6 21,38 21.2,38.2 22.1,38.2 22.3,38 22.3,37.4 22.5,37.2
+24V on Top Layer "+24V_L01_P009" (solid, remove dead copper, pour order 9): 36.1,37.2 36.3,37 36.3,36.2 36.1,36 34.4,36 34.2,35.8 34.2,34.6 34,34.4 33.1,34.4 32.9,34.6 32.9,38 33.1,38.2 34,38.2 34.2,38 34.2,37.4 34.4,37.2
NetQ3_1 on Top Layer "NETQ3_1_L01_P003" (solid, remove dead copper, pour order 3): 34.8,29.9 34.557,30.143 34.557,34.257 34.8,34.5 36.5,34.5 36.757,34.243 36.757,30.157 36.5,29.9
NetQ1_1 on Top Layer "NETQ1_1_L01_P002" (solid, remove dead copper, pour order 2): 25.8,29.9 25.6,30.1 25.6,31.6 25.9,31.9 33,31.9 33.3,31.6 33.3,30.1 33.1,29.9
NetQ2_1 on Top Layer "NETQ2_1_L01_P001" (solid, remove dead copper, pour order 1): 22.9,29.9 22.8,30 22.8,34.3 22.9,34.4 24.3,34.4 24.4,34.3 24.4,30.1 24.2,29.9
GND on Bottom Layer "GND_L02_P028" (solid, remove dead copper, pour order 28): 0.3,28.1 0.6,28.4 3.8,28.4 4.2,28.8 4.2,33.4 4.7,33.9 8.2,33.9 8.7,33.4 8.7,25 9.2,24.5 28.4,24.5 28.8,24.1 28.8,16.4 29.7,15.5 32.6,15.5 33.4,16.3 34.5,17.4 35.5,17.4 35.9,17 35.9,0.9 35.4,0.4 6.5,0.4 0.3,6.6 0.3,28
GND on Bottom Layer "GND_L02_P026" (solid, remove dead copper, pour order 26): 9.3,26.3 9.3,29.1 9.5,29.3 32.5,29.3 32.8,29 32.8,16.3 32.5,16 29.8,16 29.4,16.4 29.4,25.7 29,26.1 9.5,26.1
+24V on Bottom Layer "+24V_L02_P005" (solid, remove dead copper, pour order 5): 36.5,6.9 36.5,33.6 35.7,34.4 4.4,34.4 3.7,33.7 3.7,29.2 3.4,28.9 0.5,28.9 0.2,29.2 0.2,37.6 0.8,38.2 41,38.2 41.7,37.5 41.7,6.9 41.1,6.3 37.1,6.3
NetH5_1 on Bottom Layer "NETH5_1_L02_P025" (solid, remove dead copper, pour order 25): 35.9,38.7 36.2,39 36.2,43.3 35.9,43.6 29.3,43.6 29,43.3 29,39 29.3,38.7
NetH4_1 on Bottom Layer "NETH4_1_L02_P024" (solid, remove dead copper, pour order 24): 23.9,38.7 24.2,39 24.2,43.3 23.9,43.6 17.3,43.6 17,43.3 17,39 17.3,38.7
NetH3_1 on Bottom Layer "NETH3_1_L02_P023" (solid, remove dead copper, pour order 23): 12.4,38.7 12.7,39 12.7,43.3 12.4,43.6 5.8,43.6 5.5,43.3 5.5,39 5.8,38.7
NetQ1_1 on Bottom Layer "NETQ1_1_L02_P004" (solid, remove dead copper, pour order 4): 32.6,29.9 32.8,30.1 32.8,31.85 31.65,33 9.5,33 9.3,32.8 9.3,30.1 9.5,29.9

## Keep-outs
Keep-Out Layer:
  circle w0.254: c3,3 r1.5
  circle w0.254: c39,3 r1.5
  circle w0.254: c39,41 r1.5
  circle w0.254: c3,41 r1.5
  lines w0.254: 0.3,44 0,44 ; 0,44 0,0 42,0 42,44 0,44

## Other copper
Top Layer:
  pour cut-out: 1.6,28.7 3.9,28.7 4.1,28.9 4.1,31.2 3.9,31.4 1.6,31.4 1.4,31.2 1.4,28.9
Bottom Layer:
  pour cut-out: 28.5,0.4 28.7,0.2 30.3,0.2 30.5,0.4 30.5,11.9 30.3,12.1 28.7,12.1 28.5,11.9

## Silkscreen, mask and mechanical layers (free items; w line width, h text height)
Top Overlay:
  circle w1: c39,3 r1.934
  circle w1: c3,3 r1.934
  circle w1: c39,41 r1.934
  circle w1: c3,41 r1.934
  text "FG/TXD" at 31.2,4.78 h1
  text "OUT1" at 7,3.58 h1
  text "OUT2" at 9.8,3.58 h1
  text "DIO" at 12.9,3.58 h1
  text "CLK" at 15.4,3.58 h1
  text "GND" at 18,3.58 h1
  text "+5V" at 20.8,3.586 h1
  text "GND" at 23.9,3.58 h1
  text "GND" at 26.2,3.58 h1
  text "VSP/CLK" at 28.501,3.58 h1
  text "EN/RXD" at 33.5,3.58 h1
Bottom Overlay:
  text "摇头无感风扇_LCP037A31ES8_024VDC_SCH_V1.4_20220831" at 32.6,4.683 h1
